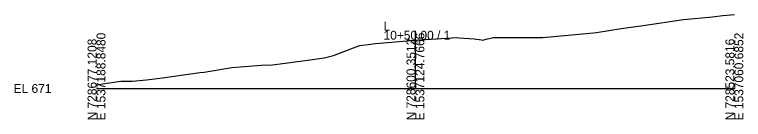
# Model space of a CAD drawing. Extents: x -26 to 1203, y -10 to 9522.
# Drawn here: x -25.7 to 202.8, y 490.3 to 523.2 of the extents above; entities that cross this region are included whole.
import ezdxf

# ---------------------------------------------------------------- set-up
doc = ezdxf.new("R2010")
doc.units = 0
for name, color, linetype in [('Default', 7, 'Continuous'), ('Exist Cross Section Cell', 7, 'Continuous'), ('Exist XS Center Line Elevation Label', 7, 'Continuous'), ('Exist XS Ground Line', 7, 'Continuous')]:
    doc.layers.add(name, color=color, linetype=linetype)

msp = doc.modelspace()

# ---------------------------------------------------------------- linework, layer by layer
at = {"layer": 'Exist Cross Section Cell'}
for p, q in [((100, 500), (100, 518.09)), ((0, 500), (100, 500)), ((100, 500), (200, 500))]:
    msp.add_line(p, q, dxfattribs=at)
at = {"layer": 'Exist XS Ground Line'}
msp.add_lwpolyline([(0, 501.03), (1.84, 501.44), (7.67, 502.31), (11.16, 502.31), (15.63, 502.66), (20.71, 503.37), (30.98, 504.8), (32.43, 504.99), (33.76, 505.14), (42.41, 506.58), (52.95, 507.37), (54.47, 507.36), (67.69, 509.04), (71.34, 509.64), (74.31, 510.36), (80.62, 512.76), (82.57, 513.45), (86.04, 513.88), (87.42, 514.06), (88.7, 514.16), (99.94, 515.15), (100, 515.15), (111.41, 515.84), (113, 515.94), (113.71, 515.87), (118.42, 515.51), (120.67, 515.24), (121.1, 515.17), (122.15, 515.42), (124.51, 515.98), (128.22, 516), (139.94, 515.97), (147.86, 516.74), (155.83, 517.48), (156.77, 517.58), (164.54, 518.76), (171.41, 519.73), (184.04, 521.58), (193.19, 522.49), (196.39, 522.84), (198.92, 523.06), (200, 523.16)], dxfattribs=at)

# ---------------------------------------------------------------- texts
at = {"layer": 'Default'}
msp.add_text('-', height=0.0001, dxfattribs=at).set_placement((0, 500))
msp.add_text('-', height=0.0001, dxfattribs=at).set_placement((0, 500))
msp.add_text('-', height=0.0001, dxfattribs=at).set_placement((0, 500))
at = {"layer": 'Exist Cross Section Cell'}
for s, p in [('L', (90, 518.09)), ('10+50.00 / 1', (90, 515.29)), ('EL 671', (-26, 498.6))]:
    msp.add_text(s, height=2.8, dxfattribs=at).set_placement(p)
for s, p in [('E 1537188.8480', (2.8, 490)), ('E 1537124.7666', (102.8, 490)), ('E 1537060.6852', (202.8, 490)), ('N 728677.1208', (0, 490)), ('N 728600.3512', (100, 490)), ('N 728523.5816', (200, 490))]:
    msp.add_text(s, height=2.8, rotation=90, dxfattribs=at).set_placement(p)
at = {"layer": 'Exist XS Center Line Elevation Label'}
msp.add_text('686.15', height=0.75, dxfattribs=at).set_placement((98.45, 514.02))

doc.saveas('drawing.dxf')
